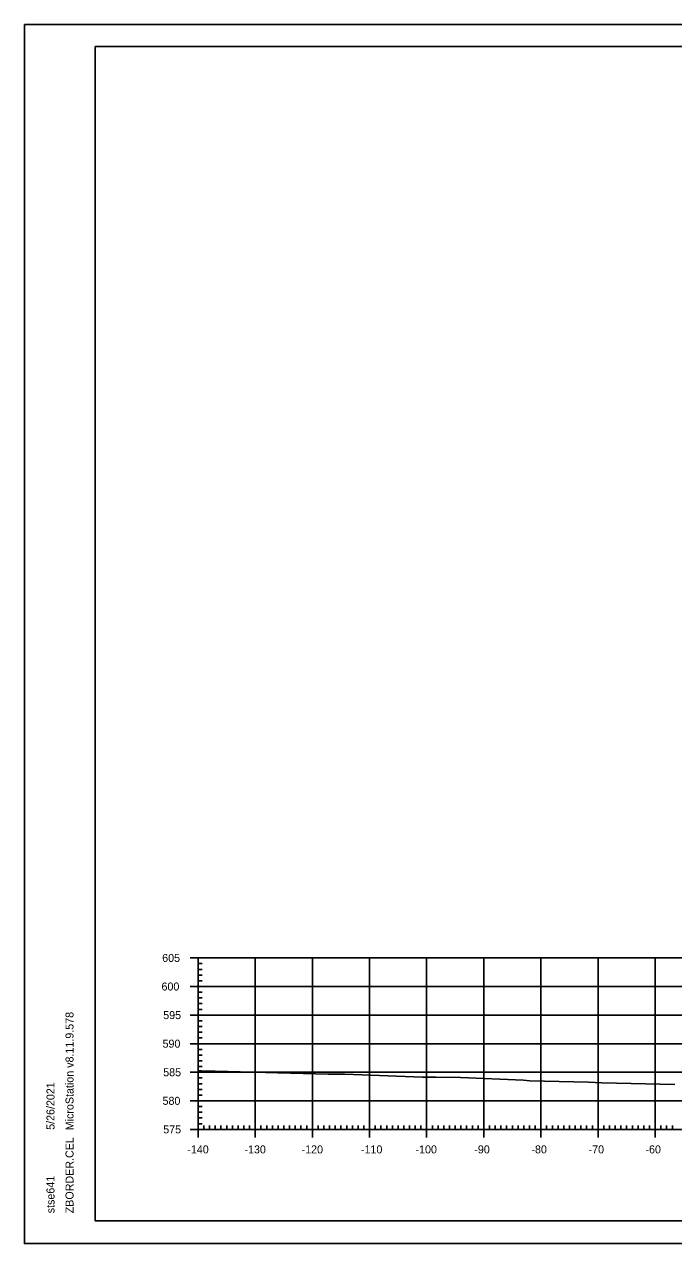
# Model space of a CAD drawing. Extents: x 961436 to 1372525, y 380079 to 2027791.
# Drawn here: x 1372191.4 to 1372305, y 380679.4 to 380892.8 of the extents above; entities that cross this region are included whole.
import ezdxf

# ---------------------------------------------------------------- set-up
doc = ezdxf.new("R2010")
doc.units = 0
for name, color, linetype in [('R_Axis', 7, 'Continuous'), ('R_Axis Annot', 7, 'Continuous'), ('R_Border', 7, 'Continuous'), ('R_Exist Surface', 7, 'Continuous'), ('R_Grid', 7, 'Continuous'), ('R_No Plot', 7, 'Continuous')]:
    doc.layers.add(name, color=color, linetype=linetype)

msp = doc.modelspace()

# ---------------------------------------------------------------- linework, layer by layer
at = {"layer": 'R_Axis'}
for p, q in [((1372220.41, 380729.42), (1372223.21, 380729.42)), ((1372221.81, 380699.42), (1372221.81, 380729.42)), ((1372221.81, 380728.42), (1372222.51, 380728.42)), ((1372221.81, 380727.42), (1372222.51, 380727.42)), ((1372220.41, 380724.42), (1372223.21, 380724.42)), ((1372221.81, 380726.42), (1372222.51, 380726.42)), ((1372221.81, 380725.42), (1372222.51, 380725.42)), ((1372221.81, 380723.42), (1372222.51, 380723.42)), ((1372221.81, 380722.42), (1372222.51, 380722.42)), ((1372221.81, 380721.42), (1372222.51, 380721.42)), ((1372221.81, 380720.42), (1372222.51, 380720.42)), ((1372220.41, 380719.42), (1372223.21, 380719.42)), ((1372221.81, 380718.42), (1372222.51, 380718.42)), ((1372221.81, 380717.42), (1372222.51, 380717.42)), ((1372221.81, 380716.42), (1372222.51, 380716.42)), ((1372220.41, 380714.42), (1372223.21, 380714.42)), ((1372221.81, 380715.42), (1372222.51, 380715.42)), ((1372221.81, 380713.42), (1372222.51, 380713.42)), ((1372221.81, 380712.42), (1372222.51, 380712.42)), ((1372221.81, 380711.42), (1372222.51, 380711.42)), ((1372221.81, 380710.42), (1372222.51, 380710.42)), ((1372220.41, 380709.42), (1372223.21, 380709.42)), ((1372221.81, 380708.42), (1372222.51, 380708.42)), ((1372221.81, 380707.42), (1372222.51, 380707.42)), ((1372221.81, 380706.42), (1372222.51, 380706.42)), ((1372221.81, 380705.42), (1372222.51, 380705.42)), ((1372220.41, 380704.42), (1372223.21, 380704.42)), ((1372221.81, 380703.42), (1372222.51, 380703.42)), ((1372221.81, 380702.42), (1372222.51, 380702.42)), ((1372221.81, 380701.42), (1372222.51, 380701.42)), ((1372220.41, 380699.42), (1372223.21, 380699.42)), ((1372221.81, 380698.02), (1372221.81, 380700.82)), ((1372221.81, 380700.42), (1372222.51, 380700.42)), ((1372221.81, 380699.42), (1372501.81, 380699.42)), ((1372222.81, 380699.42), (1372222.81, 380700.12)), ((1372223.81, 380699.42), (1372223.81, 380700.12)), ((1372224.81, 380699.42), (1372224.81, 380700.12)), ((1372225.81, 380699.42), (1372225.81, 380700.12)), ((1372226.81, 380699.42), (1372226.81, 380700.12)), ((1372227.81, 380699.42), (1372227.81, 380700.12)), ((1372228.81, 380699.42), (1372228.81, 380700.12)), ((1372229.81, 380699.42), (1372229.81, 380700.12)), ((1372230.81, 380699.42), (1372230.81, 380700.12)), ((1372231.81, 380698.02), (1372231.81, 380700.82)), ((1372232.81, 380699.42), (1372232.81, 380700.12)), ((1372233.81, 380699.42), (1372233.81, 380700.12)), ((1372234.81, 380699.42), (1372234.81, 380700.12)), ((1372235.81, 380699.42), (1372235.81, 380700.12)), ((1372236.81, 380699.42), (1372236.81, 380700.12)), ((1372237.81, 380699.42), (1372237.81, 380700.12)), ((1372238.81, 380699.42), (1372238.81, 380700.12)), ((1372239.81, 380699.42), (1372239.81, 380700.12)), ((1372240.81, 380699.42), (1372240.81, 380700.12)), ((1372241.81, 380698.02), (1372241.81, 380700.82)), ((1372242.81, 380699.42), (1372242.81, 380700.12)), ((1372243.81, 380699.42), (1372243.81, 380700.12)), ((1372244.81, 380699.42), (1372244.81, 380700.12)), ((1372245.81, 380699.42), (1372245.81, 380700.12)), ((1372246.81, 380699.42), (1372246.81, 380700.12)), ((1372247.81, 380699.42), (1372247.81, 380700.12)), ((1372248.81, 380699.42), (1372248.81, 380700.12)), ((1372249.81, 380699.42), (1372249.81, 380700.12)), ((1372250.81, 380699.42), (1372250.81, 380700.12)), ((1372251.81, 380698.02), (1372251.81, 380700.82)), ((1372252.81, 380699.42), (1372252.81, 380700.12)), ((1372253.81, 380699.42), (1372253.81, 380700.12)), ((1372254.81, 380699.42), (1372254.81, 380700.12)), ((1372255.81, 380699.42), (1372255.81, 380700.12)), ((1372256.81, 380699.42), (1372256.81, 380700.12)), ((1372257.81, 380699.42), (1372257.81, 380700.12)), ((1372258.81, 380699.42), (1372258.81, 380700.12)), ((1372259.81, 380699.42), (1372259.81, 380700.12)), ((1372260.81, 380699.42), (1372260.81, 380700.12)), ((1372261.81, 380698.02), (1372261.81, 380700.82)), ((1372262.81, 380699.42), (1372262.81, 380700.12)), ((1372263.81, 380699.42), (1372263.81, 380700.12)), ((1372264.81, 380699.42), (1372264.81, 380700.12)), ((1372265.81, 380699.42), (1372265.81, 380700.12)), ((1372266.81, 380699.42), (1372266.81, 380700.12)), ((1372267.81, 380699.42), (1372267.81, 380700.12)), ((1372268.81, 380699.42), (1372268.81, 380700.12)), ((1372269.81, 380699.42), (1372269.81, 380700.12)), ((1372270.81, 380699.42), (1372270.81, 380700.12)), ((1372271.81, 380698.02), (1372271.81, 380700.82)), ((1372272.81, 380699.42), (1372272.81, 380700.12)), ((1372273.81, 380699.42), (1372273.81, 380700.12)), ((1372274.81, 380699.42), (1372274.81, 380700.12)), ((1372275.81, 380699.42), (1372275.81, 380700.12)), ((1372276.81, 380699.42), (1372276.81, 380700.12)), ((1372277.81, 380699.42), (1372277.81, 380700.12)), ((1372278.81, 380699.42), (1372278.81, 380700.12)), ((1372279.81, 380699.42), (1372279.81, 380700.12)), ((1372280.81, 380699.42), (1372280.81, 380700.12)), ((1372281.81, 380698.02), (1372281.81, 380700.82)), ((1372282.81, 380699.42), (1372282.81, 380700.12)), ((1372283.81, 380699.42), (1372283.81, 380700.12)), ((1372284.81, 380699.42), (1372284.81, 380700.12)), ((1372285.81, 380699.42), (1372285.81, 380700.12)), ((1372286.81, 380699.42), (1372286.81, 380700.12)), ((1372287.81, 380699.42), (1372287.81, 380700.12)), ((1372288.81, 380699.42), (1372288.81, 380700.12)), ((1372289.81, 380699.42), (1372289.81, 380700.12)), ((1372290.81, 380699.42), (1372290.81, 380700.12)), ((1372291.81, 380698.02), (1372291.81, 380700.82)), ((1372292.81, 380699.42), (1372292.81, 380700.12)), ((1372293.81, 380699.42), (1372293.81, 380700.12)), ((1372294.81, 380699.42), (1372294.81, 380700.12)), ((1372295.81, 380699.42), (1372295.81, 380700.12)), ((1372296.81, 380699.42), (1372296.81, 380700.12)), ((1372297.81, 380699.42), (1372297.81, 380700.12)), ((1372298.81, 380699.42), (1372298.81, 380700.12)), ((1372299.81, 380699.42), (1372299.81, 380700.12)), ((1372300.81, 380699.42), (1372300.81, 380700.12)), ((1372301.81, 380698.02), (1372301.81, 380700.82)), ((1372302.81, 380699.42), (1372302.81, 380700.12)), ((1372303.81, 380699.42), (1372303.81, 380700.12)), ((1372304.81, 380699.42), (1372304.81, 380700.12))]:
    msp.add_line(p, q, dxfattribs=at)
at = {"layer": 'R_Border'}
for p, q in [((1372203.81, 380888.88), (1372519.99, 380888.88)), ((1372203.81, 380683.42), (1372203.81, 380888.88)), ((1372203.81, 380683.42), (1372203.81, 380683.42)), ((1372519.99, 380683.42), (1372203.81, 380683.42))]:
    msp.add_line(p, q, dxfattribs=at)
at = {"layer": 'R_Exist Surface'}
msp.add_lwpolyline([(1372221.81, 380709.7), (1372222.37, 380709.69), (1372224.81, 380709.59), (1372244.57, 380709.09), (1372247.47, 380709.09), (1372261.07, 380708.57), (1372263.41, 380708.53), (1372267.73, 380708.51), (1372278.77, 380708.05), (1372279.84, 380707.93), (1372290.14, 380707.67), (1372292.49, 380707.56), (1372305.27, 380707.27)], dxfattribs=at)
at = {"layer": 'R_Grid'}
for p, q in [((1372221.81, 380729.42), (1372501.81, 380729.42)), ((1372221.81, 380699.42), (1372221.81, 380729.42)), ((1372231.81, 380699.42), (1372231.81, 380729.42)), ((1372241.81, 380699.42), (1372241.81, 380729.42)), ((1372251.81, 380699.42), (1372251.81, 380729.42)), ((1372261.81, 380699.42), (1372261.81, 380729.42)), ((1372271.81, 380699.42), (1372271.81, 380729.42)), ((1372281.81, 380699.42), (1372281.81, 380729.42)), ((1372291.81, 380699.42), (1372291.81, 380729.42)), ((1372301.81, 380699.42), (1372301.81, 380729.42)), ((1372221.81, 380724.42), (1372501.81, 380724.42)), ((1372221.81, 380719.42), (1372501.81, 380719.42)), ((1372221.81, 380714.42), (1372501.81, 380714.42)), ((1372221.81, 380709.42), (1372501.81, 380709.42)), ((1372221.81, 380704.42), (1372501.81, 380704.42)), ((1372221.81, 380699.42), (1372501.81, 380699.42))]:
    msp.add_line(p, q, dxfattribs=at)
at = {"layer": 'R_No Plot'}
for p, q in [((1372191.41, 380892.77), (1372524.74, 380892.77)), ((1372191.41, 380679.44), (1372524.74, 380679.44))]:
    msp.add_line(p, q, dxfattribs=at)
for points in [[(1372191.4, 380892.77), (1372524.74, 380892.77), (1372524.74, 380679.43), (1372191.4, 380679.43)], [(1372437.73, 380888.88), (1372457.35, 380888.88), (1372457.35, 380879), (1372473.46, 380879), (1372496.66, 380879), (1372496.66, 380846.33), (1372519.87, 380846.33), (1372519.99, 380683.42), (1372203.81, 380683.42), (1372203.81, 380888.88)]]:
    msp.add_lwpolyline(points, close=True, dxfattribs=at)

# ---------------------------------------------------------------- texts
at = {"layer": 'R_Axis Annot'}
for s, p in [('605', (1372215.52, 380728.72)), ('600', (1372215.4, 380723.72)), ('595', (1372215.7, 380718.72)), ('590', (1372215.58, 380713.72)), ('585', (1372215.7, 380708.72)), ('580', (1372215.58, 380703.72)), ('575', (1372215.7, 380698.72)), ('-140', (1372219.92, 380695.22)), ('-130', (1372229.92, 380695.22)), ('-120', (1372239.92, 380695.22)), ('-110', (1372250.31, 380695.22)), ('-100', (1372259.86, 380695.22)), ('-90', (1372270.15, 380695.22)), ('-80', (1372280.15, 380695.22)), ('-70', (1372290.15, 380695.22)), ('-60', (1372300.11, 380695.22))]:
    msp.add_text(s, height=1.4, dxfattribs=at).set_placement(p)
at = {"layer": 'R_Border'}
for s, p in [('MicroStation v8.11.9.578', (1372200, 380699.27)), ('5/26/2021', (1372196.67, 380699.34)), ('ZBORDER.CEL', (1372200, 380684.74)), ('stse641', (1372196.67, 380684.74))]:
    msp.add_text(s, height=1.4, rotation=90, dxfattribs=at).set_placement(p)

doc.saveas('drawing.dxf')
